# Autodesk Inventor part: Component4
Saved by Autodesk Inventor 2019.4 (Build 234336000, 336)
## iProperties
Created: 2020-02
Part Number: Component4
Material: Generic
Document SubType Name: Modeling
Designer: Administrator
Density: 1 g/cm^3
Appearance: Default
Title: Component4
Author: Administrator
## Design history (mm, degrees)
feature "Body1"
feature "Body2"
feature "Body3"
body "Solid1"
body "Solid2"
body "Solid3"
